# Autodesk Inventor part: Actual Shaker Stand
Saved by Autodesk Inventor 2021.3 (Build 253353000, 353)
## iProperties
Created: 2022-03
Part Number: Actual Shaker Stand
Material: Generic
Document SubType Name: Modeling
Designer: Administrator
Density: 1 g/cm^3
Appearance: Default
Title: Actual Shaker Stand v1
Author: Administrator
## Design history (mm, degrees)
feature "Body1"
body "Solid1"
